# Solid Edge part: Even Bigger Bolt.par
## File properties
Author: m_hel
Template: iso metric part.par
Last saved by: m_hel
Revision: 5
Application: Solid Edge
Accuracy: 0,990
Username: m_hel
Material: Rubber
Face Style: Black (dull)
Fill Style: Normal
Virtual Style: Normal
Grouping: Uncategorized
LibraryName: Custom Materials
Coef. of Thermal Exp: 0.0
Thermal Conductivity: 0.0
Specific Heat: 0.0
Modulus of Elasticity: 0.0
Poisson's Ratio: 0.0
Yield Stress: 0.0
Ultimate Stress: 0.0
Elongation: 0.0
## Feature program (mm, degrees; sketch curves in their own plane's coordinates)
sketch for "unnamed Protrusion 1" plane through (0, 0, 0) normal (0, 0, 1) x-axis (1, 0, 0)
  circle centre (0, 0) radius 25
extrude "unnamed Protrusion 1" add finite 150 along -normal
sketch for "ExtrudedProtrusion_2" plane through (0, 0, 0) normal (0, 0, 1) x-axis (1, 0, 0)
  circle centre (0, 0) radius 35
extrude "ExtrudedProtrusion_2" add finite 20 along +normal
fillet "Round_1" radius 10
chamfer "Chamfer_1" setback 5
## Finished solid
Body 1: solid body, 7 faces, 6 edges, 0 vertices.
  Faces by surface: plane 3, cylinder 2, cone 1, torus 1
  Edges by curve: circle 6
Bounding box of the edges (mm; curved faces can reach further): 70.000 x 70.000 x 170.000, from (-35, -35, -150) to (35, 35, 20).
Cylindrical faces by radius (mm): R25 x1, R35 x1
Conical faces (half-angle, radius in mm at the cone's reference point): 45 deg R20 x1
Toroidal faces (ring radius, tube radius in mm): R25 r10 x1
Planar faces by outward normal: +z 1, -z 2
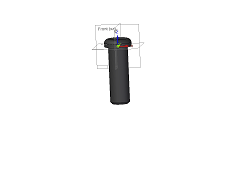
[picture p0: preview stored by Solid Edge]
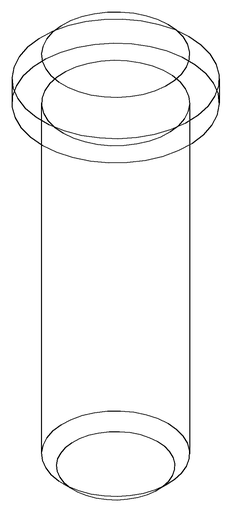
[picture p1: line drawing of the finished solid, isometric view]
